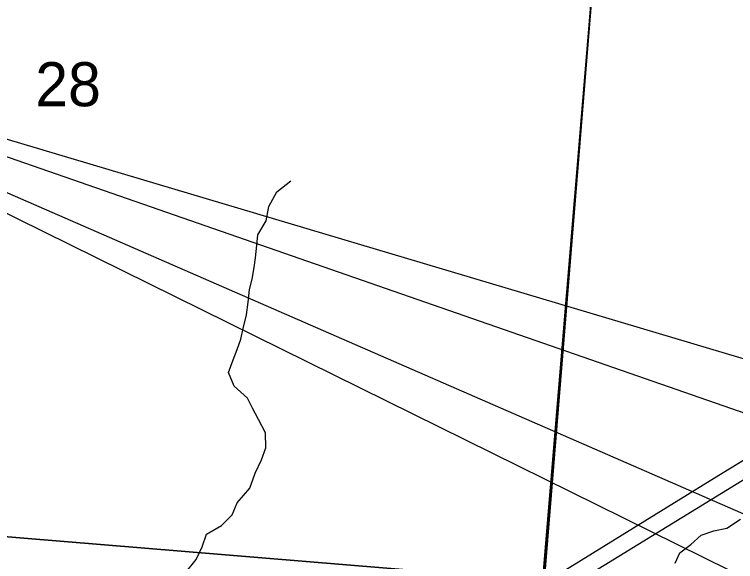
# Model space of a CAD drawing. Extents: x 0 to 34, y 0 to 22.
# Drawn here: x 4.546 to 5.23, y 17.34 to 17.859 of the extents above; entities that cross this region are included whole.
import ezdxf

# ---------------------------------------------------------------- set-up
doc = ezdxf.new("R2010")
doc.units = 0
for name, color, linetype in [('GM_X_City_Street', 7, 'Continuous'), ('GM_X_Minor_River', 7, 'Continuous'), ('GM_X_Section', 7, 'Continuous'), ('GM_X_Section_Text', 7, 'Continuous'), ('GM_X_State_Route', 7, 'Continuous'), ('SH_Text', 7, 'Continuous')]:
    doc.layers.add(name, color=color, linetype=linetype)

msp = doc.modelspace()

# ---------------------------------------------------------------- linework, layer by layer
at = {"layer": 'GM_X_City_Street'}
for points in [[(5.18938, 18.99449), (5.18499, 18.94191), (5.17869, 18.87082), (5.17419, 18.82136), (5.17043, 18.77807), (5.16278, 18.6884), (5.15895, 18.64513), (5.15801, 18.63272), (5.15779, 18.62336), (5.15806, 18.62011), (5.13386, 18.35686), (5.10093, 17.96326), (5.04713, 17.31999), (5.04559, 17.30072), (5.03201, 17.12953), (5.00768, 16.85775), (5.01969, 16.83796), (5.04285, 16.83951), (5.09535, 16.85342), (5.1216, 16.85804), (5.16946, 16.87195), (5.20959, 16.87504), (5.23893, 16.87504)], [(5.04713, 17.31999), (5.10093, 17.96326)]]:
    msp.add_lwpolyline(points, dxfattribs=at)
at = {"layer": 'GM_X_Minor_River'}
for points in [[(4.70698, 17.32796), (4.71855, 17.34226), (4.7244, 17.35434), (4.72835, 17.36645), (4.74251, 17.37464), (4.75289, 17.38477), (4.75759, 17.39611), (4.76953, 17.41001), (4.77465, 17.42439), (4.7805, 17.43685), (4.78482, 17.44819), (4.78424, 17.46263), (4.77756, 17.47524), (4.77199, 17.48594), (4.76717, 17.49549), (4.75478, 17.50665), (4.74924, 17.51963), (4.75357, 17.53173), (4.75749, 17.54156), (4.76103, 17.55139), (4.76305, 17.56162), (4.76625, 17.5745), (4.76792, 17.58663), (4.76921, 17.59839), (4.77161, 17.60824), (4.77365, 17.61923), (4.7749, 17.62871), (4.77619, 17.64047), (4.77707, 17.65034), (4.78483, 17.66354), (4.78766, 17.67718), (4.79505, 17.69114), (4.80847, 17.70162)], [(5.1728, 17.3388), (5.17749, 17.34861), (5.18784, 17.35647), (5.19744, 17.36547), (5.20965, 17.3695), (5.22184, 17.37202), (5.23486, 17.3806)]]:
    msp.add_lwpolyline(points, dxfattribs=at)
at = {"layer": 'GM_X_Section'}
for points in [[(4.13851, 18.45165), (5.13301, 18.35974), (5.04874, 17.32193), (4.09568, 17.40069)], [(5.13301, 18.35974), (6.17707, 18.26412), (6.07115, 17.24621), (5.04874, 17.32193)], [(4.09568, 17.40069), (5.04874, 17.32193), (4.96339, 16.31216), (4.00362, 16.39786)]]:
    msp.add_lwpolyline(points, close=True, dxfattribs=at)
at = {"layer": 'GM_X_State_Route'}
for points in [[(4.55943, 17.01386), (4.56735, 17.0188), (4.62449, 17.05484), (4.67542, 17.08652), (4.7277, 17.11985), (4.79865, 17.16462), (4.8512, 17.19778), (4.90644, 17.23251), (4.96189, 17.26687), (5.04736, 17.31946), (5.07299, 17.33523), (5.16553, 17.39227), (5.21848, 17.42477), (5.26608, 17.4541), (5.33488, 17.49645), (5.50695, 17.60219), (5.61533, 17.66914), (5.70531, 17.72448), (5.75297, 17.75377), (5.80855, 17.78793), (5.87826, 17.83089)], [(4.58606, 17.01137), (4.6338, 17.04143), (4.77169, 17.1289), (4.88688, 17.20158), (5.01085, 17.27867), (5.04582, 17.30019), (5.15126, 17.36503), (5.27257, 17.43947), (5.40223, 17.51898), (5.54148, 17.60436), (5.68698, 17.69452), (5.7654, 17.74273), (5.87672, 17.81131)]]:
    msp.add_lwpolyline(points, dxfattribs=at)
at = {"layer": 'SH_Text'}
for points in [[(9.32768, 15.6016), (4.19831, 17.83893), (9.32768, 15.30617)], [(9.30419, 16.32069), (4.2062, 17.84001), (9.30419, 16.06828)]]:
    msp.add_lwpolyline(points, close=True, dxfattribs=at)

# ---------------------------------------------------------------- texts
at = {"layer": 'GM_X_Section_Text'}
msp.add_text('28', height=0.041856, rotation=0.00001, dxfattribs=at).set_placement((4.56596, 17.77235))

doc.saveas('drawing.dxf')
